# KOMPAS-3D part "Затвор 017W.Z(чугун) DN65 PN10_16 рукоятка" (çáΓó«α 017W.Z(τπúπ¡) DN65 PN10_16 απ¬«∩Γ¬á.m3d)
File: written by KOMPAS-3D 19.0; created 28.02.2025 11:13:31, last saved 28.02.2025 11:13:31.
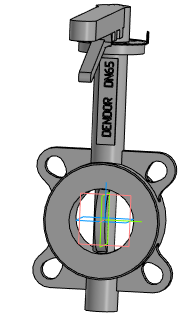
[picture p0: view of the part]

Document properties: Автор: Евгений; Полное имя файла: Затвор 017W.Z(чугун) DN65 PN10_16 рукоятка.a3d

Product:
- Part/product: Затвор 017W.Z(чугун) DN65 PN10_16 рукоятка
    Масса: 5.65752

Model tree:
1. Операция без истории:1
